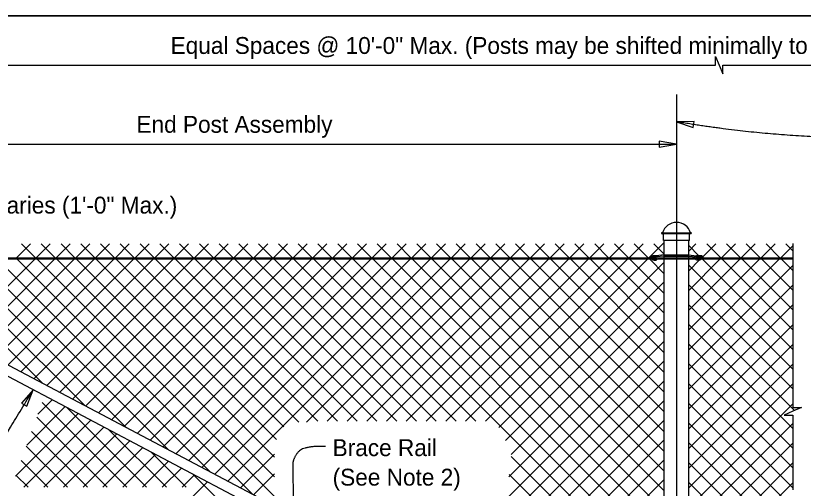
# Model space of a CAD drawing. Extents: x 0 to 41.1, y 0 to 25.9.
# Drawn here: x 6.74 to 16.13, y 20.31 to 25.95 of the extents above; entities that cross this region are included whole.
import ezdxf

# ---------------------------------------------------------------- set-up
doc = ezdxf.new("R2010")
doc.units = 0
for name, color, linetype in [('ActivePts-ConstElements', 7, 'Continuous'), ('CL_Major', 7, 'Continuous'), ('Dimension', 7, 'Continuous'), ('Miscellaneous', 7, 'Continuous'), ('Miscellaneous1', 7, 'Continuous'), ('SteelMisc', 7, 'Continuous'), ('SteelMisc_h', 7, 'Continuous'), ('TextStructures', 7, 'Continuous')]:
    doc.layers.add(name, color=color, linetype=linetype)

msp = doc.modelspace()

# ---------------------------------------------------------------- linework, layer by layer
at = {"layer": 'ActivePts-ConstElements'}
msp.add_lwpolyline([(0, 0), (41.0506, 0), (41.0506, 25.9461), (0, 25.9461)], close=True, dxfattribs=at)
msp.add_lwpolyline([(0, 0), (41.0506, 0), (41.0506, 25.9461), (0, 25.9461)], close=True, dxfattribs=at)
msp.add_lwpolyline([(0, 0), (41.0506, 0), (41.0506, 25.9461), (0, 25.9461)], close=True, dxfattribs=at)
at = {"layer": 'CL_Major'}
msp.add_line((14.615, 25.0052), (14.615, 15.2584), dxfattribs=at)
at = {"layer": 'Dimension'}
for p, q in [((0.2352, 25.3556), (13.615, 25.3556)), ((4.615, 24.4146), (14.615, 24.4146))]:
    msp.add_line(p, q, dxfattribs=at)
for points in [[(13.615, 25.3556), (15.0787, 25.3556), (15.0787, 25.4589), (15.1237, 25.3556), (15.1687, 25.2523), (15.1687, 25.3556), (28.4596, 25.3556)], [(16.002, 23.2265), (16.002, 21.2702), (16.1053, 21.2702), (16.002, 21.2252), (15.8987, 21.1802), (16.002, 21.1802), (16.002, 20.2867)]]:
    msp.add_lwpolyline(points, dxfattribs=at)
for points in [[(14.615, 24.6814), (14.815, 24.6135), (14.8262, 24.6832)], [(14.615, 24.4146), (14.4068, 24.4499), (14.4068, 24.3793)], [(6.945, 21.4806), (6.8059, 21.3216), (6.8661, 21.2847)]]:
    msp.add_lwpolyline(points, close=True, dxfattribs=at)
for points in [[(18.5966, 24.4827), (17.7933, 24.4827), (16.4039, 24.4827), (15.2225, 24.5773), (14.615, 24.6814)], [(6.6174, 20.081), (6.4865, 20.0669), (6.3036, 20.1341), (6.3121, 20.4608), (6.945, 21.4806)], [(10.4281, 20.8052), (10.1586, 20.8133), (10.0405, 20.6549), (10.0376, 20.5337), (10.0422, 20.3659), (10.0503, 19.9529)]]:
    msp.add_open_spline(points, degree=2, dxfattribs=at)
at = {"layer": 'Miscellaneous'}
for p, q in [((6.745, 23.0578), (6.9116, 23.2245)), ((6.8042, 23.2245), (6.9709, 23.0578)), ((6.9807, 23.0578), (7.1473, 23.2245)), ((7.0399, 23.2245), (7.2066, 23.0578)), ((7.2164, 23.0578), (7.383, 23.2245)), ((7.2756, 23.2245), (7.4423, 23.0578)), ((7.4521, 23.0578), (7.6187, 23.2245)), ((7.5113, 23.2245), (7.678, 23.0578)), ((7.6878, 23.0578), (7.8544, 23.2245)), ((7.747, 23.2245), (7.9137, 23.0578)), ((7.9235, 23.0578), (8.0901, 23.2245)), ((7.9827, 23.2245), (8.1494, 23.0578)), ((8.1592, 23.0578), (8.3258, 23.2245)), ((8.2184, 23.2245), (8.3851, 23.0578)), ((8.3949, 23.0578), (8.5615, 23.2245)), ((8.4541, 23.2245), (8.6208, 23.0578)), ((8.6306, 23.0578), (8.7972, 23.2245)), ((8.6898, 23.2245), (8.8565, 23.0578)), ((8.8663, 23.0578), (9.0329, 23.2245)), ((8.9255, 23.2245), (9.0922, 23.0578)), ((9.102, 23.0578), (9.2687, 23.2245)), ((9.1612, 23.2245), (9.3279, 23.0578)), ((9.3377, 23.0578), (9.5044, 23.2245)), ((9.3969, 23.2245), (9.5636, 23.0578)), ((9.5734, 23.0578), (9.7401, 23.2245)), ((9.6326, 23.2245), (9.7993, 23.0578)), ((9.8091, 23.0578), (9.9758, 23.2245)), ((9.8683, 23.2245), (10.035, 23.0578)), ((10.0448, 23.0578), (10.2115, 23.2245)), ((10.104, 23.2245), (10.2707, 23.0578)), ((10.2805, 23.0578), (10.4472, 23.2245)), ((10.3397, 23.2245), (10.5064, 23.0578)), ((10.5162, 23.0578), (10.6829, 23.2245)), ((10.5754, 23.2245), (10.7421, 23.0578)), ((10.7519, 23.0578), (10.9186, 23.2245)), ((10.8111, 23.2245), (10.9778, 23.0578)), ((10.9876, 23.0578), (11.1543, 23.2245)), ((11.0468, 23.2245), (11.2135, 23.0578)), ((11.2233, 23.0578), (11.39, 23.2245)), ((11.2825, 23.2245), (11.4492, 23.0578)), ((11.459, 23.0578), (11.6257, 23.2245)), ((11.5182, 23.2245), (11.6849, 23.0578)), ((11.6947, 23.0578), (11.8614, 23.2245)), ((11.7539, 23.2245), (11.9206, 23.0578)), ((11.9304, 23.0578), (12.0971, 23.2245)), ((11.9896, 23.2245), (12.1563, 23.0578)), ((12.1661, 23.0578), (12.3328, 23.2245)), ((12.2253, 23.2245), (12.392, 23.0578)), ((12.336, 21.1064), (14.4692, 23.2396)), ((12.4018, 23.0578), (12.5685, 23.2245)), ((12.461, 23.2245), (12.6277, 23.0578)), ((12.6375, 23.0578), (12.8042, 23.2245)), ((12.6967, 23.2245), (12.8634, 23.0578)), ((12.8732, 23.0578), (13.0399, 23.2245)), ((12.9324, 23.2245), (13.0991, 23.0578)), ((13.1089, 23.0578), (13.2756, 23.2245)), ((13.1681, 23.2245), (13.3348, 23.0578)), ((13.3446, 23.0578), (13.5113, 23.2245)), ((13.4038, 23.2245), (13.5705, 23.0578)), ((13.5803, 23.0578), (13.747, 23.2245)), ((13.6396, 23.2245), (13.8062, 23.0578)), ((13.816, 23.0578), (13.9827, 23.2245)), ((13.8753, 23.2245), (14.0419, 23.0578)), ((14.0517, 23.0578), (14.2184, 23.2245)), ((14.111, 23.2245), (14.2776, 23.0578)), ((14.2874, 23.0578), (14.4541, 23.2245)), ((14.3467, 23.2245), (14.4692, 23.1019)), ((14.7609, 23.1379), (14.8475, 23.2245)), ((14.7609, 23.2036), (14.8832, 23.0814)), ((14.928, 23.0694), (15.0832, 23.2245)), ((14.9757, 23.2245), (15.1424, 23.0578)), ((15.1522, 23.0578), (15.3189, 23.2245)), ((15.2114, 23.2245), (15.3781, 23.0578)), ((15.3879, 23.0578), (15.5546, 23.2245)), ((15.4471, 23.2245), (15.6138, 23.0578)), ((15.6236, 23.0578), (15.7903, 23.2245)), ((15.6828, 23.2245), (15.8495, 23.0578)), ((15.8593, 23.0578), (16.002, 23.2005)), ((15.9185, 23.2245), (16.002, 23.1411)), ((5.8071, 23.0431), (7.5577, 21.2925)), ((6.0252, 22.1023), (6.9659, 23.0431)), ((6.0428, 23.0431), (8.0575, 21.0283)), ((6.1794, 22.0209), (7.2016, 23.0431)), ((6.2785, 23.0431), (8.5574, 20.7642)), ((6.3336, 21.9394), (7.4373, 23.0431)), ((6.4878, 21.8579), (7.673, 23.0431)), ((6.5142, 23.0431), (9.0572, 20.5)), ((6.642, 21.7764), (7.9087, 23.0431)), ((6.7499, 23.0431), (9.5571, 20.2359)), ((6.7962, 21.6949), (8.1444, 23.0431)), ((6.9504, 21.6134), (8.3801, 23.0431)), ((6.9856, 23.0431), (9.8224, 20.2063)), ((7.1046, 21.5319), (8.6158, 23.0431)), ((7.2213, 23.0431), (9.8224, 20.442)), ((7.2589, 21.4504), (8.8515, 23.0431)), ((7.4131, 21.3689), (9.0872, 23.0431)), ((7.457, 23.0431), (9.8224, 20.6777)), ((7.5673, 21.2874), (9.3229, 23.0431)), ((7.6927, 23.0431), (9.8467, 20.8891)), ((7.7215, 21.2059), (9.5586, 23.0431)), ((7.8757, 21.1244), (9.7943, 23.0431)), ((7.9284, 23.0431), (9.9312, 21.0403)), ((8.0299, 21.0429), (10.03, 23.0431)), ((8.1641, 23.0431), (10.1124, 21.0948)), ((8.1841, 20.9614), (10.2657, 23.0431)), ((8.3383, 20.88), (10.5014, 23.0431)), ((8.3998, 23.0431), (10.3365, 21.1064)), ((8.4925, 20.7985), (10.7372, 23.0431)), ((8.6355, 23.0431), (10.5722, 21.1064)), ((8.6467, 20.717), (10.9729, 23.0431)), ((8.8009, 20.6355), (11.2086, 23.0431)), ((8.8712, 23.0431), (10.8079, 21.1064)), ((8.9552, 20.554), (11.4443, 23.0431)), ((9.1069, 23.0431), (11.0436, 21.1064)), ((9.1094, 20.4725), (11.68, 23.0431)), ((9.2636, 20.391), (11.9157, 23.0431)), ((9.3426, 23.0431), (11.2793, 21.1064)), ((9.5783, 23.0431), (11.515, 21.1064)), ((9.814, 23.0431), (11.7507, 21.1064)), ((10.0497, 23.0431), (11.9864, 21.1064)), ((10.2043, 21.096), (12.1514, 23.0431)), ((10.2854, 23.0431), (12.2221, 21.1064)), ((10.4504, 21.1064), (12.3871, 23.0431)), ((10.5211, 23.0431), (14.4692, 19.095)), ((10.6861, 21.1064), (12.6228, 23.0431)), ((10.7568, 23.0431), (14.4692, 19.3307)), ((10.9218, 21.1064), (12.8585, 23.0431)), ((10.9925, 23.0431), (14.4692, 19.5664)), ((11.1575, 21.1064), (13.0942, 23.0431)), ((11.2282, 23.0431), (14.4692, 19.8021)), ((11.3932, 21.1064), (13.3299, 23.0431)), ((11.4639, 23.0431), (14.4692, 20.0378)), ((11.6289, 21.1064), (13.5656, 23.0431)), ((11.6996, 23.0431), (14.4692, 20.2735)), ((11.8646, 21.1064), (13.8013, 23.0431)), ((11.9353, 23.0431), (14.4692, 20.5092)), ((12.1003, 21.1064), (14.037, 23.0431)), ((12.1711, 23.0431), (14.4692, 20.7449)), ((12.4068, 23.0431), (14.4692, 20.9806)), ((12.6425, 23.0431), (14.4692, 21.2163)), ((12.8782, 23.0431), (14.4692, 21.452)), ((13.1139, 23.0431), (14.4692, 21.6877)), ((13.3496, 23.0431), (14.4692, 21.9234)), ((13.5853, 23.0431), (14.4692, 22.1591)), ((13.821, 23.0431), (14.4692, 22.3948)), ((14.0567, 23.0431), (14.4692, 22.6305)), ((14.2924, 23.0431), (14.4692, 22.8662)), ((14.7609, 21.9594), (15.8446, 23.0431)), ((14.7609, 22.4308), (15.3732, 23.0431)), ((14.7609, 22.6665), (15.1375, 23.0431)), ((14.7609, 22.9022), (14.8904, 23.0317)), ((14.7653, 22.1995), (15.6089, 23.0431)), ((14.9165, 23.0578), (14.921, 23.0623)), ((14.9214, 23.0431), (16.002, 21.9626)), ((15.1572, 23.0431), (16.002, 22.1983)), ((15.3929, 23.0431), (16.002, 22.434)), ((15.6286, 23.0431), (16.002, 22.6697)), ((15.8643, 23.0431), (16.002, 22.9054)), ((12.4951, 21.0298), (14.4692, 23.0039)), ((14.7609, 22.9679), (16.002, 21.7268)), ((14.7609, 21.7237), (16.002, 22.9648)), ((5.7518, 22.8627), (7.0578, 21.5566)), ((12.5756, 20.8746), (14.4692, 22.7682)), ((14.7609, 22.7322), (16.002, 21.4911)), ((14.7609, 21.488), (16.002, 22.7291)), ((12.6439, 20.7072), (14.4692, 22.5325)), ((14.7609, 22.4965), (16.023, 21.2344)), ((14.7609, 21.2523), (16.002, 22.4934)), ((12.6167, 20.4443), (14.4692, 22.2968)), ((14.7609, 22.2608), (16.002, 21.0197)), ((14.7609, 21.0166), (16.002, 22.2577)), ((11.5767, 19.1686), (14.4692, 22.0611)), ((14.7609, 22.0251), (16.002, 20.784)), ((14.7609, 20.7809), (16.002, 22.022)), ((11.7309, 19.0871), (14.4692, 21.8254)), ((14.7609, 21.7894), (16.002, 20.5483)), ((14.7609, 20.5452), (16.002, 21.7863)), ((11.8851, 19.0056), (14.4692, 21.5897)), ((14.7609, 21.5537), (16.002, 20.3126)), ((14.7609, 20.3095), (16.002, 21.5506)), ((7.0006, 21.1922), (7.1701, 21.3617)), ((7.0502, 21.3286), (8.0609, 20.3178)), ((12.0393, 18.9241), (14.4692, 21.354)), ((6.8661, 20.822), (7.3243, 21.2802)), ((7.3455, 21.269), (8.2966, 20.3178)), ((14.7609, 21.318), (16.002, 20.0769)), ((14.7609, 20.0738), (16.002, 21.3149)), ((6.7317, 20.4518), (7.4785, 21.1987)), ((6.9874, 21.1557), (7.8252, 20.3178)), ((6.8334, 20.3178), (7.6327, 21.1172)), ((12.1936, 18.8426), (14.4692, 21.1183)), ((14.7609, 21.0823), (16.002, 19.8412)), ((14.7609, 19.8381), (16.002, 21.0792)), ((6.9246, 20.9828), (7.5895, 20.3178)), ((7.0691, 20.3178), (7.7869, 21.0357)), ((7.3048, 20.3178), (7.9412, 20.9542)), ((7.8453, 21.0048), (8.5323, 20.3178)), ((7.5405, 20.3178), (8.0954, 20.8727)), ((12.3478, 18.7611), (14.4692, 20.8826)), ((6.8618, 20.8099), (7.3538, 20.3178)), ((7.7762, 20.3178), (8.2496, 20.7912)), ((14.7609, 20.8466), (16.002, 19.6055)), ((14.7609, 19.6024), (16.002, 20.8435)), ((8.0119, 20.3178), (8.4038, 20.7097)), ((8.3452, 20.7407), (8.768, 20.3178)), ((9.4178, 20.3095), (9.8224, 20.7141)), ((12.6449, 20.6836), (14.4692, 18.8593)), ((6.7989, 20.637), (7.1181, 20.3178)), ((8.2476, 20.3178), (8.558, 20.6282)), ((12.502, 18.6796), (14.4692, 20.6469)), ((14.7609, 20.6109), (16.002, 19.3698)), ((14.7609, 19.3667), (16.002, 20.6078)), ((8.4833, 20.3178), (8.7122, 20.5467)), ((8.845, 20.4766), (11.9157, 17.4059)), ((9.572, 20.228), (9.8224, 20.4784)), ((6.7361, 20.4641), (6.8824, 20.3178)), ((8.719, 20.3178), (8.8664, 20.4652)), ((8.8145, 20.1777), (9.0206, 20.3838)), ((12.6214, 20.4714), (14.4692, 18.6236)), ((12.6562, 18.5982), (14.4692, 20.4112)), ((14.7609, 20.3752), (15.9395, 19.1966)), ((14.7609, 19.131), (16.002, 20.3721))]:
    msp.add_line(p, q, dxfattribs=at)
at = {"layer": 'Miscellaneous1'}
msp.add_lwpolyline([(0, 25.9461), (41.0506, 25.9461), (41.0506, 0), (0, 0)], close=True, dxfattribs=at)
at = {"layer": 'SteelMisc'}
for p, q in [((14.4427, 23.3564), (14.7873, 23.3564)), ((14.7873, 23.3442), (14.4427, 23.3442)), ((14.461, 23.2645), (14.461, 23.3442)), ((14.7691, 23.2645), (14.7691, 23.3442)), ((14.7691, 23.2645), (14.461, 23.2645)), ((14.4692, 17.6192), (14.4692, 23.2644)), ((14.7609, 17.6192), (14.7609, 23.2644)), ((5.8052, 23.0578), (14.2941, 23.0578)), ((5.8052, 23.0431), (14.3207, 23.0431)), ((14.304, 23.0578), (14.3172, 23.0578)), ((14.4692, 23.0904), (14.3743, 23.0793)), ((14.4692, 23.0759), (14.3766, 23.0664)), ((14.3856, 23.0431), (14.4692, 23.0431)), ((14.387, 23.0578), (14.4692, 23.0578)), ((14.4692, 23.0904), (14.7604, 23.0921)), ((14.4692, 23.0759), (14.7604, 23.0776)), ((14.7604, 23.0921), (14.8547, 23.081)), ((14.7604, 23.0776), (14.8525, 23.0682)), ((14.7609, 23.0578), (14.8413, 23.0578)), ((14.7609, 23.0431), (14.8439, 23.0431)), ((14.9067, 23.0431), (16.002, 23.0431)), ((14.9116, 23.0578), (14.9269, 23.0578)), ((14.9353, 23.0578), (16.002, 23.0578)), ((14.2677, 17.7466), (5.0181, 22.6346)), ((14.2117, 17.6406), (4.962, 22.5285))]:
    msp.add_line(p, q, dxfattribs=at)
for centre, start, end in [((14.4429, 23.3502), 91.1647, 268.8353), ((14.7872, 23.3502), 271.1647, 88.8353)]:
    msp.add_arc(centre, 0.00613, start, end, dxfattribs=at)
for centre, major_axis, ratio, start_param, end_param in [((14.6157, 23.3154), (0.1711, 0), 0.957868, 0.252602, 2.888574), ((14.3283, 23.0436), (0.0373, 0), 0.957868, 1.486836, 3.108042), ((14.3494, 23.0039), (-0.0724, 0), 0.957868, 5.162149, 5.652106), ((14.3419, 23.0555), (-0.0249, 0), 0.957868, 6.009018, 7.089857), ((14.3408, 23.058), (0.023, 0), 0.957868, 1.29026, 2.970541), ((14.3433, 23.0515), (0.0231, 0), 0.957868, 3.779554, 4.879821), ((14.3595, 23.0527), (0.0295, 0), 0.957868, 1.220941, 4.039556), ((14.373, 23.0544), (-0.0303, -0.0108), 0.724765, 4.35367, 6.324556), ((14.3494, 23.0458), (0.0206, -0.0021), 0.798607, 4.32653, 5.220153), ((14.3629, 23.0458), (0.0206, -0.0021), 0.798607, 3.333154, 5.220153), ((14.3697, 23.0504), (-0.0139, 0), 0.957868, 5.22362, 6.905413), ((14.364, 23.048), (-0.00795, 0), 0.957868, 6.140374, 9.314262), ((14.3781, 23.0415), (-0.0259, 0), 0.957868, 4.777514, 5.62749), ((14.3624, 23.0538), (0.0119, 0), 0.957868, 5.725876, 7.416677), ((14.3555, 23.0646), (0.0391, 0), 0.957868, 5.082588, 5.41974), ((14.3624, 23.0538), (0.0119, 0), 0.957868, 5.639684, 5.723117), ((14.3626, 23.0525), (0.0251, 0), 0.957868, 5.531357, 6.227833), ((14.3626, 23.0525), (0.0251, 0), 0.957868, 0.407687, 0.609214), ((14.8661, 23.0543), (-0.0251, 0), 0.957868, 0.055352, 0.751829), ((14.8661, 23.0543), (-0.0251, 0), 0.957868, 5.673972, 5.875498), ((14.8732, 23.0664), (-0.0391, 0), 0.957868, 0.863445, 1.200597), ((14.8556, 23.0562), (0.0303, -0.0108), 0.724765, 6.241815, 8.212701), ((14.8506, 23.0433), (0.0259, 0), 0.957868, 0.655696, 1.505671), ((14.8663, 23.0556), (-0.0119, 0), 0.957868, 5.149694, 6.840495), ((14.8663, 23.0556), (-0.0119, 0), 0.957868, 0.560069, 0.643501), ((14.8646, 23.0498), (0.00795, 0), 0.957868, 3.252108, 6.425997), ((14.8658, 23.0476), (-0.0206, -0.0021), 0.798607, 1.063032, 2.950031), ((14.8691, 23.0544), (-0.0295, 0), 0.957868, 2.243629, 5.062245), ((14.859, 23.0521), (0.0139, 0), 0.957868, 5.660958, 7.342751), ((14.8792, 23.0476), (-0.0206, -0.0021), 0.798607, 1.063032, 1.956656), ((14.8879, 23.0598), (-0.023, 0), 0.957868, 3.312645, 4.992926), ((14.8853, 23.0533), (-0.0231, 0), 0.957868, 1.403365, 2.503632), ((14.9004, 23.0453), (-0.0373, 0), 0.957868, 3.175144, 4.79635), ((14.8867, 23.0573), (0.0249, 0), 0.957868, 5.476514, 6.557353), ((14.8792, 23.0056), (0.0724, 0), 0.957868, 0.631079, 1.121037)]:
    msp.add_ellipse(centre, major_axis=major_axis, ratio=ratio, start_param=start_param, end_param=end_param, dxfattribs=at)
at = {"layer": 'SteelMisc_h'}
for p, q in [((14.4692, 23.0578), (14.7609, 23.0578)), ((14.4692, 23.0431), (14.7609, 23.0431))]:
    msp.add_line(p, q, dxfattribs=at)

# ---------------------------------------------------------------- texts
at = {"layer": 'TextStructures'}
for s, p in [('Equal Spaces @ 10\'-0" Max. (Posts may be shifted minimally to meet required clearances)', (8.5826, 25.4902)), ('End Post Assembly', (8.1753, 24.5492)), ('Varies (1\'-0" Max.)', (6.4474, 23.5846)), ('Brace Rail', (10.5146, 20.6895)), ('(See Note 2)', (10.5146, 20.3375))]:
    msp.add_text(s, height=0.2016, dxfattribs=at).set_placement(p)

doc.saveas('drawing.dxf')
